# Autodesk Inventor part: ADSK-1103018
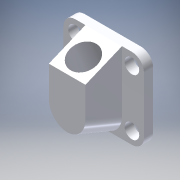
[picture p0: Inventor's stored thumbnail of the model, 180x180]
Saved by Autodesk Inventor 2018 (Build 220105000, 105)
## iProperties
Shininess: 50.0
Length Units: 11272
Angle Units: 11279
Time Units: 11290
Mass Units: 11286
Length Display Precision: 4
Angle Display Precision: 2
Compacted: True
Created: 2000-09
Part Number: ADSK-1103018
Document SubType Name: Modeling
Description: INTAKE BODY
Mass: 1.50386 g
Surface Area: 7.7204 cm^2
Volume: 0.554931 cm^3
Density: 2.71 g/cm^3
Material: Aluminum-6061
Appearance: Aluminum - Flat
Density: 0.0
Volumn: 0.0
Area: 0.0
PropertySet Name: Model Information
Control State: 0
Master: False
Checked Out: False
Author: Autodesk, Inc.
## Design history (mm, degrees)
node "Extrusion1" dims "d2" = 1.5875, "d3" = 0
  sketch "Sketch3"
    geometry: L1 (-6.985, 4.889)-(-6.985, -4.889); L2 (6.985, -4.889)-(6.985, 4.889); L3 (4.889, 6.985)-(-4.889, 6.985); L4 (-4.889, -6.985)-(4.889, -6.985); A1 r 2.096 centre (-4.889, 4.889) between (-4.889, 6.985) and (-6.985, 4.889); A2 r 2.096 centre (-4.889, -4.889) between (-6.985, -4.889) and (-4.889, -6.985); A3 r 2.096 centre (4.889, -4.889) between (4.889, -6.985) and (6.985, -4.889); A4 r 2.095 centre (4.889, 4.889) between (6.985, 4.889) and (4.889, 6.985)
    constraints: 8 end point, 8 point on circle, 6 tangent, 4 centre point, 3 equal radius, 3 perpendicular, 1 horizontal, 1 parallel, 1 vertical, 1 other
    dimensions: "d0" = 13.97 distance between parallel lines of L2 L1; "d1" = 2.0955 radius of A2
node "Extrusion2" dims "d5" = 1.5875, "d6" = 0
  sketch "Sketch4"
    geometry: C1 r 1.27 at (-4.889, 4.889); C2 r 1.27 at (4.889, 4.889); C3 r 1.27 at (4.889, -4.889); C4 r 1.27 at (-4.889, -4.889); 4 further points
    constraints: 4 centre point, 4 coincident, 3 equal radius
    dimensions: "d4" = 2.54 diameter of C4
workplane "Work Plane1"
workplane "Work Plane2"
node "Extrusion3" dims "d11" = 1.5875, "d12" = 0
  sketch "Sketch5"
    geometry: L1 (1.587, 9.779)-(1.587, 0) reference; L2 (0, 11.874)-(1.587, 11.874) reference; L3 (0, -2.096)-(1.587, -2.096) reference; L4 (1.587, 11.874)-(1.587, -2.096); L5 (1.587, -2.096)-(7.938, 0.535); L6 (7.938, 0.535)-(7.938, 9.244); L7 (7.938, 9.244)-(1.587, 11.874)
    constraints: 8 end point, 1 collinear, 1 equal length, 1 parallel
    dimensions: "d9" = 45 deg angle of L5 L7; "d10" = 6.35 distance between parallel lines of L1 L6
node "Fillet1" dims "d15" = 3.175
node "Hole2" dims "d42" = 4.7625, "d43" = 9.525, "d44" = 6.35, "d45" = 60 deg, "d46" = 7.62, "d47" = 118 deg
  sketch "Sketch10"
    geometry: L1 (0, 0)-(6.35, 0) reference; L2 (0, -6.873)-(0, 0) reference; 1 further point
    dimensions: "d40" = 3.81 distance from line of L1 point (3.175, -3.81); "d41" = 3.175 distance from line of L2 point (3.175, -3.81)
body "Solid1"
other parameters: "d7" = -3.81, "d8" = -3.81
